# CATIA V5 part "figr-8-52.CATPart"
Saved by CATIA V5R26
Part number: Part1
Bounding box of the stored display mesh (mm): x -37.5 to 37.5, y -150 to 150, z 0 to 10
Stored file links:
  D:\_Deepak\CATIA\CATIA V5-6R2016_Deepak\Resources\Part files\Partfiles\c08_catia_v5_6r2016_prt\figr-8-52.CATPart
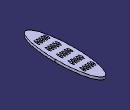
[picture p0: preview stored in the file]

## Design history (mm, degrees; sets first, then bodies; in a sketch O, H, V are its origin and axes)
Body1 (main body)
  Sketch1 on xy-plane, origin (0, 0, 0), H (1, 0, 0), V (0, 1, 0)
    circle A1 centre (0, 0) radius 75
    point P1 (0, 75)
    radius A1 = 75
    coincidence: A1 P1, P1 V
  Pad1: profile Sketch1, direction (0, 0, 1), length 10
  Sketch2 on face of Pad1, origin (0, 0, 10), H (1, 0, 0), V (0, 1, 0)
    circle A1 centre (35, -45) radius 6
    point P1 (35, -45)
    distance P1 H = 45
    distance V P1 = 35
    radius A1 = 6
  Pocket1: profile Sketch2, direction (0, 0, -1), through (limit type 3)
  RectPattern1: of Pocket1, direction 1 instances 5, spacing 19, along xy-plane reversed, direction 2 instances 5, spacing 22, along xy-plane
  Affinity1: ToTransfor RectPattern1, RatioX 0.5, RatioY 2, RatioZ 1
